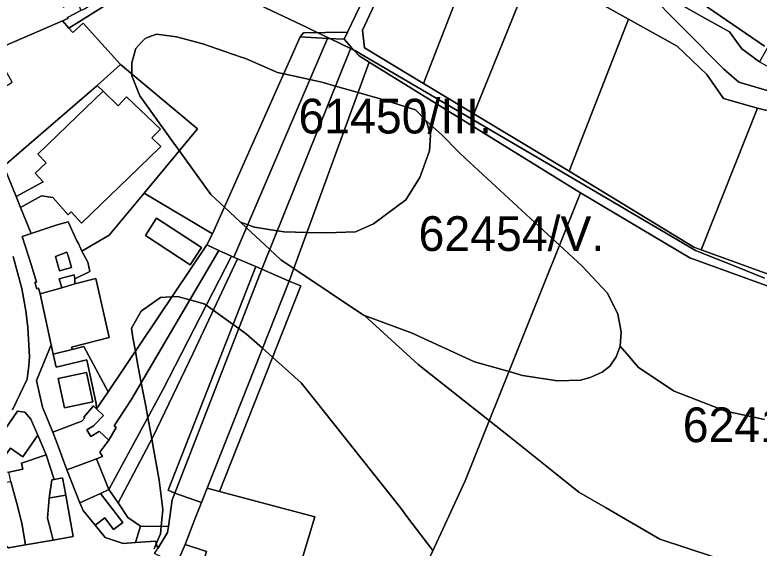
# Model space of a CAD drawing. Extents: x -522079 to -518792, y -1142400 to -1139961.
# Drawn here: x -520324.1 to -520002.4, y -1141173.1 to -1140942.7 of the extents above; entities that cross this region are included whole.
import ezdxf

# ---------------------------------------------------------------- set-up
doc = ezdxf.new("R2010")
doc.units = 0
for name, color, linetype in [('Hranice parcel', 7, 'Continuous'), ('Parcelní čísla', 7, 'Continuous'), ('Poz předměty', 7, 'Continuous'), ('Vnitřní kresba', 7, 'Continuous'), ('Značky bodu BP', 7, 'Continuous'), ('Značky kultur', 7, 'Continuous')]:
    doc.layers.add(name, color=color, linetype=linetype)

msp = doc.modelspace()

# ---------------------------------------------------------------- linework, layer by layer
at = {"layer": 'Hranice parcel'}
for points in [[(-520079.53, -1141019.58), (-520170.88, -1140963.13), (-520175.23, -1140960.44), (-520178.74, -1140956.58), (-520181.77, -1140953.24), (-520180.26, -1140950.09), (-520156.19, -1140899.86), (-520151.68, -1140896.26), (-520149.94, -1140892.73), (-520146.75, -1140896.12), (-520154.18, -1140907.23), (-520173.77, -1140949.3), (-520172.97, -1140956.99), (-520147.43, -1140972.36), (-520125.63, -1140985.48), (-520084.54, -1141010.19), (-520030.55, -1141043.1), (-520027.48, -1141044.21), (-519988.12, -1141058.45), (-519949.16, -1141072.54), (-519944.08, -1141074.41), (-519948.1, -1141084.44), (-519951.21, -1141077.01), (-520032.33, -1141047.7)], [(-520301.23, -1140944.23), (-520301.37, -1140943.86), (-520295.5, -1140940.8), (-520294.04, -1140940.04), (-520260.36, -1140918.14), (-520255, -1140914.65), (-520250.52, -1140910), (-520250.18, -1140910.34), (-520237.12, -1140923.52), (-520246.32, -1140932.55), (-520257.36, -1140921.21), (-520300.74, -1140948.36), (-520303.52, -1140945.28)], [(-520301.23, -1140944.23), (-520303.52, -1140945.28), (-520311.37, -1140948.65), (-520312.42, -1140949.1), (-520330.57, -1140956.9), (-520333.07, -1140958.03), (-520347.56, -1140964.58), (-520357.85, -1140939.9), (-520356.86, -1140939.57), (-520333.64, -1140931.91), (-520328.35, -1140930.16), (-520327.1, -1140929.75), (-520320.68, -1140927.43), (-520309.29, -1140923.33), (-520304.25, -1140936.55), (-520303.17, -1140939.4), (-520297.35, -1140935.94), (-520295.5, -1140940.8), (-520301.37, -1140943.86)], [(-520002.28, -1140962.91), (-519999.3, -1140964.63), (-519986.94, -1140971.3), (-519974.08, -1140974.02), (-519965.47, -1140973.69), (-519979.37, -1140981.19), (-520011.16, -1140971.75), (-520017.69, -1140966.19), (-520051.93, -1140931.48), (-520046.33, -1140932.29), (-520029.76, -1140941.98), (-520015.17, -1140949.95), (-520009.84, -1140957.29)], [(-520333.07, -1140958.03), (-520330.57, -1140956.9), (-520312.42, -1140949.1), (-520311.37, -1140948.65), (-520303.52, -1140945.28), (-520300.74, -1140948.36), (-520299.04, -1140950.24), (-520294.61, -1140946.2), (-520278.46, -1140964.1), (-520288.51, -1140973.21), (-520288.83, -1140973.5), (-520322.15, -1141002.36), (-520328.8, -1141008.12), (-520339.88, -1140982.4), (-520336.31, -1140980.12), (-520328.21, -1140974.96), (-520328.8, -1140974.04), (-520325.3, -1140971.81)], [(-520181.77, -1140953.24), (-520189.01, -1140952.86), (-520200.79, -1140952.24), (-520199.25, -1140950.43), (-520180.26, -1140950.09)], [(-520310.61, -1141006.67), (-520315.31, -1141011.02), (-520311.83, -1141014.78), (-520323.52, -1141021.14), (-520328.8, -1141008.12), (-520322.15, -1141002.36), (-520288.83, -1140973.5), (-520288.51, -1140973.21), (-520285.91, -1140975.7), (-520297.15, -1140986.51), (-520314.09, -1141002.81)], [(-520261.15, -1140992.05), (-520264.81, -1140995.88), (-520260.98, -1140999.54), (-520270.67, -1141008.89), (-520295.32, -1141032.65), (-520299.78, -1141027.82), (-520301.02, -1141029.07), (-520307.7, -1141021.63), (-520312.58, -1141020.86), (-520321.6, -1141025.87), (-520323.52, -1141021.14), (-520311.83, -1141014.78), (-520315.31, -1141011.02), (-520310.61, -1141006.67), (-520314.09, -1141002.81), (-520297.15, -1140986.51), (-520285.91, -1140975.7), (-520279.41, -1140981.92), (-520275.75, -1140978.09)], [(-520262.81, -1141030.49), (-520243.34, -1141043.16), (-520248.33, -1141050.65), (-520267.66, -1141037.99)], [(-520317.05, -1141050.62), (-520320.97, -1141038.48), (-520317.01, -1141037.16), (-520314.43, -1141036.29), (-520305.82, -1141033.42), (-520301.05, -1141032.14), (-520297.24, -1141040.29), (-520296.61, -1141041.42), (-520295.18, -1141044.79), (-520292.48, -1141049.55), (-520291.66, -1141053.56), (-520298.11, -1141056.69), (-520298.5, -1141055.07), (-520304.9, -1141056.77), (-520303.8, -1141060.64), (-520313.18, -1141063.23), (-520313.88, -1141060.82), (-520314.63, -1141061.07), (-520315.46, -1141058.39), (-520314.7, -1141058.15)], [(-520306.5, -1141047.04), (-520301.57, -1141045.28), (-520300.92, -1141047.3), (-520299.56, -1141051.86), (-520304.78, -1141053.3)], [(-520301.57, -1141045.28), (-520306.5, -1141047.04), (-520304.78, -1141053.3), (-520299.56, -1141051.86), (-520300.92, -1141047.3)], [(-520217.35, -1141052.59), (-520254.95, -1141149.39), (-520257.88, -1141148.13), (-520219.97, -1141051.46)], [(-520308.39, -1141085.31), (-520313.18, -1141063.23), (-520303.8, -1141060.64), (-520298.12, -1141058.85), (-520289.01, -1141056.56), (-520283.36, -1141082.1), (-520299.54, -1141086.27), (-520299.29, -1141087.24), (-520307.52, -1141089.35)], [(-520298.11, -1141056.69), (-520298.12, -1141058.85), (-520303.8, -1141060.64), (-520304.9, -1141056.77), (-520298.5, -1141055.07)], [(-520307.67, -1141123.05), (-520312.08, -1141112.23), (-520314.66, -1141100.66), (-520308.39, -1141085.31), (-520307.52, -1141089.35), (-520306.28, -1141094.87), (-520292.97, -1141091.81), (-520289, -1141110.56), (-520288.75, -1141112.92), (-520290.03, -1141111.68), (-520294.23, -1141116.47), (-520293.88, -1141116.78), (-520295.14, -1141118.22), (-520296.78, -1141118.85)], [(-520283.75, -1141105.56), (-520288.75, -1141112.92), (-520289, -1141110.56), (-520292.97, -1141091.81), (-520306.28, -1141094.87), (-520307.52, -1141089.35), (-520299.29, -1141087.24), (-520294.2, -1141085.93)], [(-520305.34, -1141099.75), (-520293.08, -1141097.17), (-520290.35, -1141109.96), (-520302.64, -1141112.56)], [(-520290.35, -1141109.96), (-520293.08, -1141097.17), (-520305.34, -1141099.75), (-520302.64, -1141112.56)], [(-520333.47, -1141129.1), (-520335.21, -1141135.1), (-520336.61, -1141141.05), (-520337.89, -1141145.94), (-520338.1, -1141152.71), (-520338.08, -1141155.23), (-520336.67, -1141159.38), (-520330.81, -1141170.06), (-520326.87, -1141172.95), (-520319.49, -1141171.67), (-520307.53, -1141169.64), (-520298.87, -1141168.07), (-520302.11, -1141150.23), (-520303.47, -1141142.76), (-520307.07, -1141143.41), (-520310.58, -1141132.78), (-520314.1, -1141124.27), (-520317.19, -1141117.39), (-520319.83, -1141114.42), (-520322.89, -1141113.99)], [(-520328.05, -1141132.9), (-520333.47, -1141129.1), (-520322.89, -1141113.99), (-520319.83, -1141114.42), (-520317.19, -1141117.39), (-520314.1, -1141124.27), (-520320.65, -1141133.62), (-520325.95, -1141129.91)], [(-520301.56, -1141139.26), (-520305.82, -1141127.93), (-520307.67, -1141123.05), (-520296.78, -1141118.85), (-520295.14, -1141118.22), (-520293.88, -1141116.78), (-520294.23, -1141116.47), (-520290.03, -1141111.68), (-520288.75, -1141112.92), (-520285.76, -1141115.8), (-520290.1, -1141120.29), (-520292.95, -1141121.95), (-520291.23, -1141124.89), (-520287.92, -1141122.9), (-520287.59, -1141122.55), (-520283.49, -1141126.48), (-520287.28, -1141131.69), (-520286.17, -1141133.59), (-520288.84, -1141134.57), (-520294.61, -1141136.72)], [(-520326.63, -1141140.31), (-520336.61, -1141141.05), (-520335.21, -1141135.1), (-520333.47, -1141129.1), (-520328.05, -1141132.9), (-520325.95, -1141129.91), (-520320.65, -1141133.62), (-520314.1, -1141124.27), (-520310.58, -1141132.78), (-520321.22, -1141136.45), (-520320.69, -1141138.98)], [(-520320.69, -1141138.98), (-520321.22, -1141136.45), (-520310.58, -1141132.78), (-520307.07, -1141143.41), (-520308.03, -1141143.58), (-520309.19, -1141151.52), (-520309.97, -1141160.19), (-520308.56, -1141165.63), (-520307.53, -1141169.64), (-520319.49, -1141171.67), (-520321.08, -1141162.3), (-520323.24, -1141153.9), (-520325.8, -1141144.31), (-520326.63, -1141140.31)], [(-520283.41, -1141147.79), (-520287.07, -1141149.47), (-520296.03, -1141153.59), (-520301.56, -1141139.26), (-520294.61, -1141136.72), (-520288.84, -1141134.57)], [(-520319.49, -1141171.67), (-520326.87, -1141172.95), (-520330.81, -1141170.06), (-520336.67, -1141159.38), (-520338.08, -1141155.23), (-520338.1, -1141152.71), (-520337.89, -1141145.94), (-520325.8, -1141144.31), (-520323.24, -1141153.9), (-520321.08, -1141162.3)], [(-520296.03, -1141153.59), (-520287.07, -1141149.47), (-520277.44, -1141162.04), (-520281.38, -1141165.06), (-520285.21, -1141160.06), (-520289.43, -1141163.17), (-520294.54, -1141156.83)], [(-520309.19, -1141151.52), (-520307.91, -1141151.29), (-520302.11, -1141150.23), (-520298.87, -1141168.07), (-520307.53, -1141169.64), (-520308.56, -1141165.63), (-520309.97, -1141160.19)], [(-520269.77, -1141163.56), (-520257.71, -1141163.82), (-520258.09, -1141166.43), (-520262.34, -1141173.28), (-520263.33, -1141170.08), (-520271.87, -1141170.72)]]:
    msp.add_lwpolyline(points, close=True, dxfattribs=at)
for points in [[(-520328.8, -1141008.12), (-520323.52, -1141021.14), (-520321.6, -1141025.87), (-520317.01, -1141037.16), (-520320.97, -1141038.48), (-520317.05, -1141050.62), (-520314.7, -1141058.15), (-520315.46, -1141058.39), (-520314.63, -1141061.07), (-520313.88, -1141060.82), (-520313.18, -1141063.23), (-520308.39, -1141085.31), (-520314.66, -1141100.66), (-520312.08, -1141112.23), (-520307.67, -1141123.05), (-520305.82, -1141127.93), (-520301.56, -1141139.26), (-520296.03, -1141153.59), (-520294.54, -1141156.83), (-520289.43, -1141163.17), (-520285.07, -1141168.6), (-520277.22, -1141171.12), (-520271.87, -1141170.72), (-520263.33, -1141170.08), (-520262.34, -1141173.28)], [(-520324.76, -1141047.17), (-520321.07, -1141060.89), (-520319.27, -1141070.53), (-520318.44, -1141077.73), (-520317.76, -1141090.48), (-520318.04, -1141094.37), (-520318.78, -1141100.08), (-520325.12, -1141113.35)], [(-520325.12, -1141113.35), (-520318.78, -1141100.08), (-520318.04, -1141094.37), (-520317.76, -1141090.48), (-520318.44, -1141077.73), (-520319.27, -1141070.53), (-520321.07, -1141060.89), (-520324.76, -1141047.17)]]:
    msp.add_lwpolyline(points, dxfattribs=at)
at = {"layer": 'Parcelní čísla'}
for points in [[(-520205.51, -1141057.7), (-520170.88, -1140963.13), (-520079.53, -1141019.58), (-520129.38, -1141144.09), (-520158.56, -1141206.98), (-520178.85, -1141202.22), (-520209, -1141207.86), (-520194.38, -1141159.65), (-520235.62, -1141148.58), (-520200.4, -1141059.73)], [(-520079.53, -1141019.58), (-520032.33, -1141047.7), (-519951.21, -1141077.01), (-519948.1, -1141084.44), (-519980.55, -1141165.39), (-520014.17, -1141252.24), (-520020.92, -1141254.2), (-520158.56, -1141206.98), (-520129.38, -1141144.09)]]:
    msp.add_lwpolyline(points, close=True, dxfattribs=at)
at = {"layer": 'Poz předměty'}
for points in [[(-520022.73, -1140882.19), (-519999.48, -1140892), (-519969.45, -1140904.62), (-520002.28, -1140962.91), (-520009.84, -1140957.29), (-520015.17, -1140949.95), (-520029.76, -1140941.98), (-520046.33, -1140932.29), (-520051.93, -1140931.48), (-520055.67, -1140929.56)], [(-520154.18, -1140907.23), (-520136.24, -1140924.81), (-520129.31, -1140925.55), (-520147.43, -1140972.36), (-520172.97, -1140956.99), (-520173.77, -1140949.3)], [(-520129.31, -1140925.55), (-520124.49, -1140925.8), (-520100.12, -1140914.78), (-520097.88, -1140916.76), (-520125.63, -1140985.48), (-520147.43, -1140972.36)], [(-520097.88, -1140916.76), (-520079.83, -1140932.73), (-520058.84, -1140944.58), (-520084.54, -1141010.19), (-520125.63, -1140985.48)], [(-520017.73, -1140978.78), (-520003.11, -1140982.94), (-520027.48, -1141044.21), (-520030.55, -1141043.1), (-520084.54, -1141010.19), (-520058.84, -1140944.58), (-520037.81, -1140956.24), (-520025.01, -1140968.52)], [(-520003.11, -1140982.94), (-519978.85, -1140988.86), (-519967.54, -1140984.38), (-519966.67, -1140989.91), (-519961.08, -1140991.39), (-519988.12, -1141058.45), (-520027.48, -1141044.21)]]:
    msp.add_lwpolyline(points, close=True, dxfattribs=at)
at = {"layer": 'Vnitřní kresba'}
for points in [[(-519978.85, -1140988.86), (-520003.11, -1140982.94), (-520017.73, -1140978.78), (-520025.01, -1140968.52), (-520037.81, -1140956.24), (-520058.84, -1140944.58), (-520079.83, -1140932.73)], [(-520051.93, -1140931.48), (-520017.69, -1140966.19), (-520011.16, -1140971.75), (-519979.37, -1140981.19)]]:
    msp.add_lwpolyline(points, dxfattribs=at)
at = {"layer": 'Značky bodu BP'}
for points in [[(-520331.96, -1140791.24), (-520323.76, -1140801.76), (-520319.61, -1140804.3), (-520310.14, -1140810.09), (-520298.45, -1140817.25), (-520292.94, -1140818.09), (-520262.02, -1140822.82), (-520257.78, -1140824.09), (-520218.2, -1140835.96), (-520202.12, -1140840.78), (-520201.07, -1140841.21), (-520186.01, -1140847.28), (-520160.33, -1140857.64), (-520147.26, -1140862.91), (-520139.14, -1140866.18), (-520138.61, -1140866.5), (-520123.75, -1140875.26), (-520086.66, -1140897.15), (-520050.3, -1140921.84), (-520027.38, -1140937.41), (-520000, -1140956.26)], [(-520000, -1140956.26), (-520027.38, -1140937.41), (-520050.3, -1140921.84), (-520086.66, -1140897.15), (-520123.75, -1140875.26), (-520138.61, -1140866.5), (-520139.14, -1140866.18), (-520147.26, -1140862.91), (-520160.33, -1140857.64), (-520186.01, -1140847.28), (-520201.07, -1140841.21), (-520202.12, -1140840.78), (-520218.2, -1140835.96), (-520257.78, -1140824.09), (-520262.02, -1140822.82), (-520292.94, -1140818.09), (-520298.45, -1140817.25), (-520310.14, -1140810.09), (-520319.61, -1140804.3), (-520323.76, -1140801.76), (-520331.96, -1140791.24)], [(-520000, -1141056.45), (-520011.71, -1141051.75), (-520029.88, -1141044.45), (-520090.04, -1141009.08), (-520177.16, -1140958.1), (-520177.51, -1140957.94), (-520179, -1140957.22), (-520187.97, -1140952.91), (-520193.37, -1140950.32), (-520197.48, -1140948.35), (-520236.79, -1140929.49), (-520241.05, -1140927.38), (-520260.08, -1140917.96), (-520260.95, -1140917.52), (-520263.93, -1140916.05), (-520267.12, -1140914.47), (-520274.28, -1140910.93), (-520277.76, -1140909.2), (-520287.26, -1140905.6), (-520291.47, -1140904.01), (-520313.41, -1140895.68), (-520320.28, -1140893.08), (-520338.07, -1140887.2)], [(-520338.07, -1140887.2), (-520320.28, -1140893.08), (-520313.41, -1140895.68), (-520291.47, -1140904.01), (-520287.26, -1140905.6), (-520277.76, -1140909.2), (-520274.28, -1140910.93), (-520267.12, -1140914.47), (-520263.93, -1140916.05), (-520260.95, -1140917.52), (-520260.08, -1140917.96), (-520241.05, -1140927.38), (-520236.79, -1140929.49), (-520197.48, -1140948.35), (-520193.37, -1140950.32), (-520187.97, -1140952.91), (-520179, -1140957.22), (-520177.51, -1140957.94), (-520177.16, -1140958.1), (-520090.04, -1141009.08), (-520029.88, -1141044.45), (-520011.71, -1141051.75), (-520000, -1141056.45)], [(-520000, -1141117.5), (-520014.8, -1141114.31), (-520017.19, -1141113.8), (-520039.12, -1141105.26), (-520054.5, -1141095.09), (-520059.59, -1141089.22), (-520062.47, -1141085.9), (-520062.05, -1141079.59), (-520063.52, -1141072.02), (-520067.92, -1141062.99), (-520078.82, -1141051.21), (-520088.61, -1141042.27), (-520093.91, -1141037.44), (-520097.47, -1141034.19), (-520129.32, -1141004.76), (-520132.12, -1141001.95), (-520139.58, -1140994.46), (-520146.08, -1140988.57), (-520150.9, -1140983.74), (-520165.15, -1140979.32), (-520175.69, -1140976.27), (-520185.52, -1140973.44), (-520191.34, -1140971.76), (-520196.59, -1140970.61), (-520207.87, -1140968.15), (-520210.62, -1140967.55), (-520224.66, -1140961.45), (-520226.23, -1140960.91), (-520242.89, -1140955.15), (-520254.2, -1140952.21), (-520262.79, -1140950.95), (-520266.47, -1140952.33), (-520267.82, -1140952.84), (-520269.45, -1140954.64), (-520271.81, -1140957.25), (-520271.92, -1140957.68), (-520273.48, -1140963.35), (-520273.48, -1140968.25), (-520273.48, -1140969.02), (-520270.13, -1140977.64), (-520256.93, -1140995.93), (-520253.02, -1141001.35), (-520239.33, -1141020.32), (-520233.52, -1141025.76), (-520226.54, -1141032.29), (-520223.97, -1141034.69), (-520213.91, -1141044.05), (-520209.15, -1141048.48), (-520203.51, -1141052.25), (-520173.32, -1141072.44), (-520172.96, -1141072.58), (-520149.72, -1141093.77), (-520118.98, -1141118.13), (-520110.78, -1141124.63), (-520092.7, -1141139.06), (-520080.35, -1141148.92), (-520068.83, -1141155.61), (-520045.33, -1141169.27), (-520022.1, -1141176.82)], [(-520143.35, -1141174.2), (-520154.17, -1141159.99), (-520157.27, -1141155.91), (-520194.6, -1141108.87), (-520200.28, -1141101.71), (-520212.66, -1141090.67), (-520217.03, -1141086.78), (-520223.89, -1141080.66), (-520227.3, -1141078.21), (-520229.77, -1141076.44), (-520238.3, -1141070.33), (-520241.32, -1141068.17), (-520242.25, -1141067.5), (-520248.42, -1141065.81), (-520253.79, -1141064.34), (-520256.23, -1141064.52), (-520256.72, -1141064.56), (-520261.14, -1141064.87), (-520269.53, -1141070.66), (-520273.73, -1141078.03), (-520273.04, -1141082.04), (-520272, -1141088.04), (-520271.1, -1141093.29), (-520269.44, -1141101.63), (-520267.43, -1141111.71), (-520266.53, -1141116.71), (-520264.87, -1141125.95), (-520263.98, -1141130.92), (-520261.66, -1141143.81), (-520260.09, -1141156.44), (-520260.82, -1141163.75), (-520261.14, -1141166.96), (-520262.1, -1141169.26), (-520262.95, -1141171.3), (-520263.83, -1141173.4)], [(-520263.83, -1141173.4), (-520262.95, -1141171.3), (-520262.1, -1141169.26), (-520261.14, -1141166.96), (-520260.82, -1141163.75), (-520260.09, -1141156.44), (-520261.66, -1141143.81), (-520263.98, -1141130.92), (-520264.87, -1141125.95), (-520266.53, -1141116.71), (-520267.43, -1141111.71), (-520269.44, -1141101.63), (-520271.1, -1141093.29), (-520272, -1141088.04), (-520273.04, -1141082.04), (-520273.73, -1141078.03), (-520269.53, -1141070.66), (-520261.14, -1141064.87), (-520256.72, -1141064.56), (-520256.23, -1141064.52), (-520253.79, -1141064.34), (-520248.42, -1141065.81), (-520242.25, -1141067.5), (-520241.32, -1141068.17), (-520238.3, -1141070.33), (-520229.77, -1141076.44), (-520227.3, -1141078.21), (-520223.89, -1141080.66), (-520217.03, -1141086.78), (-520212.66, -1141090.67), (-520200.28, -1141101.71), (-520194.6, -1141108.87), (-520157.27, -1141155.91), (-520154.17, -1141159.99), (-520143.35, -1141174.2)], [(-520022.1, -1141176.82), (-520045.33, -1141169.27), (-520068.83, -1141155.61), (-520080.35, -1141148.92), (-520092.7, -1141139.06), (-520110.78, -1141124.63), (-520118.98, -1141118.13), (-520149.72, -1141093.77), (-520172.96, -1141072.58), (-520152.37, -1141080.22), (-520125.34, -1141092.62), (-520110.46, -1141096.84), (-520104.59, -1141098.51), (-520089.5, -1141100.82), (-520079.66, -1141100.61), (-520075.46, -1141099.35), (-520070.23, -1141097.04), (-520066.87, -1141094.52), (-520064.15, -1141090.52), (-520062.47, -1141085.9), (-520059.59, -1141089.22), (-520054.5, -1141095.09), (-520039.12, -1141105.26), (-520017.19, -1141113.8), (-520014.8, -1141114.31), (-520000, -1141117.5)]]:
    msp.add_lwpolyline(points, dxfattribs=at)
for points in [[(-520176.88, -1141036.5), (-520189.25, -1141036.92), (-520197.83, -1141036.73), (-520207.68, -1141036.5), (-520210.68, -1141036.01), (-520220.47, -1141034.4), (-520223.41, -1141033.38), (-520226.54, -1141032.29), (-520233.52, -1141025.76), (-520239.33, -1141020.32), (-520253.02, -1141001.35), (-520256.93, -1140995.93), (-520270.13, -1140977.64), (-520273.48, -1140969.02), (-520273.48, -1140968.25), (-520273.48, -1140963.35), (-520271.92, -1140957.68), (-520271.81, -1140957.25), (-520269.45, -1140954.64), (-520267.82, -1140952.84), (-520266.47, -1140952.33), (-520262.79, -1140950.95), (-520254.2, -1140952.21), (-520242.89, -1140955.15), (-520226.23, -1140960.91), (-520224.66, -1140961.45), (-520210.62, -1140967.55), (-520207.87, -1140968.15), (-520196.59, -1140970.61), (-520191.34, -1140971.76), (-520185.52, -1140973.44), (-520175.69, -1140976.27), (-520165.15, -1140979.32), (-520150.9, -1140983.74), (-520146.08, -1140988.57), (-520144.4, -1140994.67), (-520144.82, -1141001.4), (-520149.01, -1141012.96), (-520155.09, -1141022.62), (-520169.13, -1141032.93)], [(-520097.47, -1141034.19), (-520093.91, -1141037.44), (-520088.61, -1141042.27), (-520078.82, -1141051.21), (-520067.92, -1141062.99), (-520063.52, -1141072.02), (-520062.05, -1141079.59), (-520062.47, -1141085.9), (-520064.15, -1141090.52), (-520066.87, -1141094.52), (-520070.23, -1141097.04), (-520075.46, -1141099.35), (-520079.66, -1141100.61), (-520089.5, -1141100.82), (-520104.59, -1141098.51), (-520110.46, -1141096.84), (-520125.34, -1141092.62), (-520152.37, -1141080.22), (-520172.96, -1141072.58), (-520173.32, -1141072.44), (-520203.51, -1141052.25), (-520209.15, -1141048.48), (-520213.91, -1141044.05), (-520223.97, -1141034.69), (-520226.54, -1141032.29), (-520223.41, -1141033.38), (-520220.47, -1141034.4), (-520210.68, -1141036.01), (-520207.68, -1141036.5), (-520197.83, -1141036.73), (-520189.25, -1141036.92), (-520176.88, -1141036.5), (-520169.13, -1141032.93), (-520155.09, -1141022.62), (-520149.01, -1141012.96), (-520144.82, -1141001.4), (-520144.4, -1140994.67), (-520146.08, -1140988.57), (-520139.58, -1140994.46), (-520132.12, -1141001.95), (-520129.32, -1141004.76)]]:
    msp.add_lwpolyline(points, close=True, dxfattribs=at)
at = {"layer": 'Značky kultur'}
for points in [[(-520278.46, -1140964.1), (-520294.61, -1140946.2), (-520299.04, -1140950.24), (-520300.74, -1140948.36), (-520257.36, -1140921.21), (-520246.32, -1140932.55), (-520237.12, -1140923.52), (-520250.18, -1140910.34), (-520199.46, -1140857.65), (-520181.95, -1140869.32), (-520182.55, -1140869.96), (-520164.55, -1140881.96), (-520151.68, -1140896.26), (-520156.19, -1140899.86), (-520180.26, -1140950.09), (-520199.25, -1140950.43), (-520200.79, -1140952.24), (-520238.67, -1141037.33), (-520268.23, -1141019.69), (-520245.17, -1140991.88)], [(-520235.95, -1141044.56), (-520241.17, -1141042.05), (-520238.67, -1141037.33), (-520200.79, -1140952.24), (-520189.01, -1140952.86), (-520229.4, -1141047.39), (-520230.46, -1141046.93)], [(-520181.77, -1140953.24), (-520178.74, -1140956.58), (-520217.35, -1141052.59), (-520219.97, -1141051.46), (-520227.89, -1141048.04), (-520229.4, -1141047.39), (-520189.01, -1140952.86)], [(-520217.35, -1141052.59), (-520178.74, -1140956.58), (-520175.23, -1140960.44), (-520170.88, -1140963.13), (-520205.51, -1141057.7)], [(-520283.27, -1141037.84), (-520295.18, -1141044.79), (-520296.61, -1141041.42), (-520297.24, -1141040.29), (-520301.05, -1141032.14), (-520305.82, -1141033.42), (-520314.43, -1141036.29), (-520317.01, -1141037.16), (-520321.6, -1141025.87), (-520312.58, -1141020.86), (-520307.7, -1141021.63), (-520301.02, -1141029.07), (-520299.78, -1141027.82), (-520295.32, -1141032.65), (-520270.67, -1141008.89), (-520260.98, -1140999.54), (-520264.81, -1140995.88), (-520261.15, -1140992.05), (-520275.75, -1140978.09), (-520279.41, -1140981.92), (-520285.91, -1140975.7), (-520288.51, -1140973.21), (-520278.46, -1140964.1), (-520245.17, -1140991.88), (-520268.23, -1141019.69)], [(-520291.66, -1141053.56), (-520292.48, -1141049.55), (-520295.18, -1141044.79), (-520283.27, -1141037.84), (-520268.23, -1141019.69), (-520238.67, -1141037.33), (-520241.17, -1141042.05), (-520283.75, -1141105.56), (-520294.2, -1141085.93), (-520299.29, -1141087.24), (-520299.54, -1141086.27), (-520283.36, -1141082.1), (-520289.01, -1141056.56), (-520298.12, -1141058.85), (-520298.11, -1141056.69)], [(-520262.81, -1141030.49), (-520267.66, -1141037.99), (-520248.33, -1141050.65), (-520243.34, -1141043.16)], [(-520280.3, -1141121.02), (-520283.49, -1141126.48), (-520287.59, -1141122.55), (-520287.92, -1141122.9), (-520291.23, -1141124.89), (-520292.95, -1141121.95), (-520290.1, -1141120.29), (-520285.76, -1141115.8), (-520288.75, -1141112.92), (-520283.75, -1141105.56), (-520241.17, -1141042.05), (-520235.95, -1141044.56), (-520273.79, -1141109.04), (-520281.17, -1141120.23)], [(-520288.84, -1141134.57), (-520286.17, -1141133.59), (-520287.28, -1141131.69), (-520283.49, -1141126.48), (-520280.3, -1141121.02), (-520281.17, -1141120.23), (-520273.79, -1141109.04), (-520235.95, -1141044.56), (-520230.46, -1141046.93), (-520260.05, -1141104.78), (-520283.41, -1141147.79)], [(-520229.4, -1141047.39), (-520227.89, -1141048.04), (-520246.96, -1141088.89), (-520264.44, -1141125.14), (-520279.46, -1141153.62), (-520283.41, -1141147.79), (-520260.05, -1141104.78), (-520230.46, -1141046.93)], [(-520264.44, -1141125.14), (-520246.96, -1141088.89), (-520227.89, -1141048.04), (-520219.97, -1141051.46), (-520257.88, -1141148.13), (-520254.95, -1141149.39), (-520256.03, -1141152.27), (-520257.71, -1141163.82), (-520269.77, -1141163.56), (-520275.19, -1141159.91), (-520279.46, -1141153.62)], [(-520205.51, -1141057.7), (-520240.94, -1141147.15), (-520243.41, -1141153.37), (-520254.95, -1141149.39), (-520217.35, -1141052.59)], [(-520200.4, -1141059.73), (-520235.62, -1141148.58), (-520240.94, -1141147.15), (-520205.51, -1141057.7)], [(-520309.19, -1141151.52), (-520308.03, -1141143.58), (-520307.07, -1141143.41), (-520303.47, -1141142.76), (-520302.11, -1141150.23), (-520307.91, -1141151.29)], [(-520275.19, -1141159.91), (-520269.77, -1141163.56), (-520271.87, -1141170.72), (-520277.22, -1141171.12), (-520285.07, -1141168.6), (-520289.43, -1141163.17), (-520285.21, -1141160.06), (-520281.38, -1141165.06), (-520277.44, -1141162.04), (-520287.07, -1141149.47), (-520283.41, -1141147.79), (-520279.46, -1141153.62)], [(-520243.41, -1141153.37), (-520246.26, -1141160.66), (-520250.48, -1141171.53), (-520253.97, -1141179.43), (-520255.51, -1141182.9), (-520257.33, -1141187.03), (-520257.63, -1141187.7), (-520267.83, -1141182.58), (-520262.19, -1141185.29), (-520260.45, -1141181.87), (-520258.53, -1141178.07), (-520263.7, -1141175.46), (-520262.34, -1141173.28), (-520258.09, -1141166.43), (-520257.71, -1141163.82), (-520256.03, -1141152.27), (-520254.95, -1141149.39)], [(-520209, -1141207.86), (-520222.29, -1141209.66), (-520219.73, -1141201.41), (-520215.84, -1141187.57), (-520242.23, -1141179.94), (-520242.77, -1141179.78), (-520241.26, -1141174.54), (-520250.48, -1141171.53), (-520246.26, -1141160.66), (-520243.41, -1141153.37), (-520240.94, -1141147.15), (-520235.62, -1141148.58), (-520194.38, -1141159.65)], [(-520241.26, -1141174.54), (-520242.77, -1141179.78), (-520243.9, -1141183.68), (-520253.97, -1141179.43), (-520250.48, -1141171.53)]]:
    msp.add_lwpolyline(points, close=True, dxfattribs=at)

# ---------------------------------------------------------------- texts
at = {"layer": 'Značky bodu BP'}
for s, rotation, p in [('61450/III.', 360, (-520201.49, -1140993.94)), ('62454/V.', 0, (-520149.59, -1141044.7)), ('62411/III.', 0, (-520035.39, -1141127.33))]:
    msp.add_text(s, height=15, rotation=rotation, dxfattribs=at).set_placement(p)

doc.saveas('drawing.dxf')
